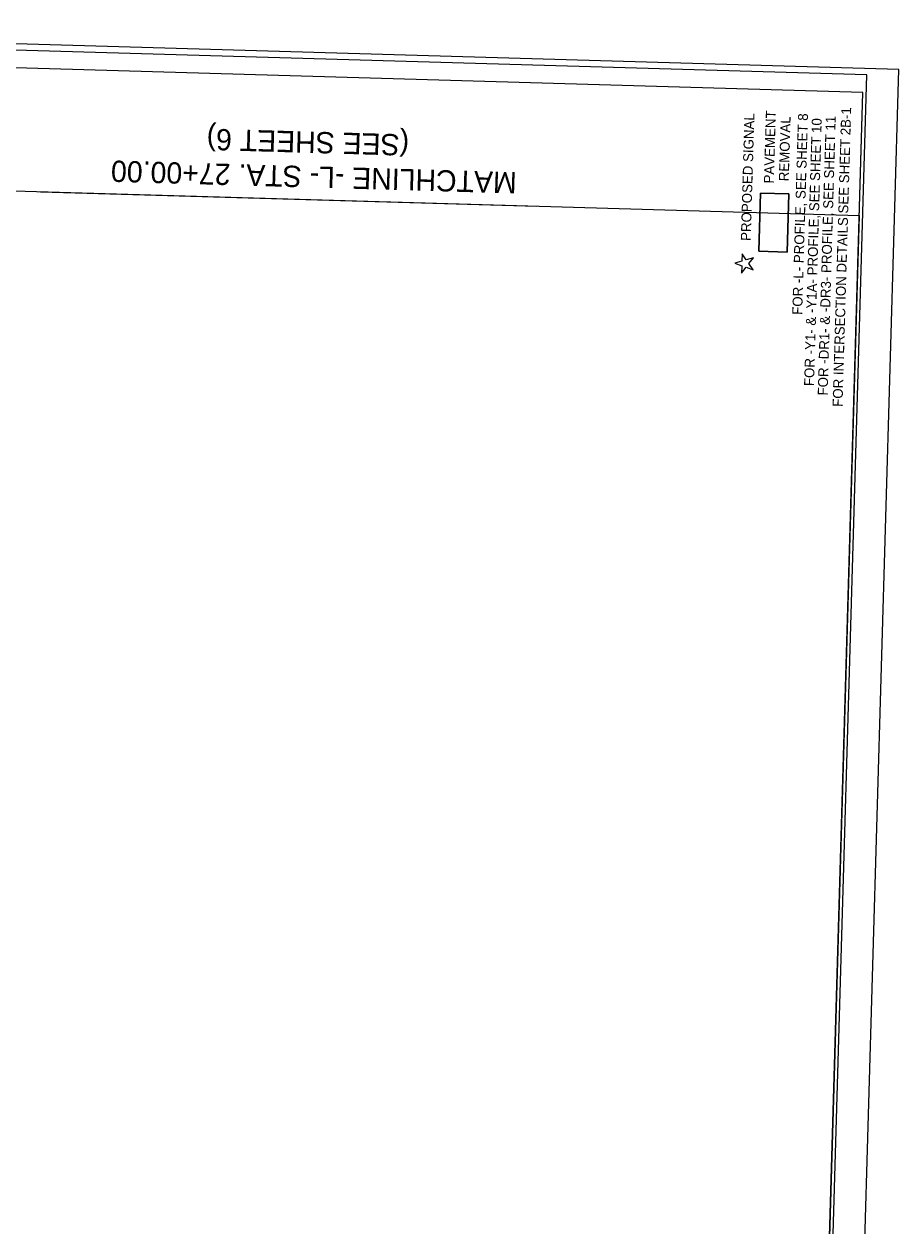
# Model space of a CAD drawing. Extents: x 2097000 to 2098148, y 684979 to 687012.
# Drawn here: x 2097532 to 2098148, y 685995 to 686842 of the extents above; entities that cross this region are included whole.
import ezdxf

# ---------------------------------------------------------------- set-up
doc = ezdxf.new("R2010")
doc.units = 0
for name, color, linetype in [('Default', 7, 'Continuous'), ('Matchline', 7, 'Continuous'), ('Matchline Text', 7, 'Continuous'), ('Prop Dimension Text', 7, 'Continuous'), ('Prop RDY Traffic Signal CELL', 7, 'Continuous'), ('Prop Rem of Exist Asph Pvmt', 7, 'Continuous'), ('Sheet Layout Plan Border', 7, 'Continuous'), ('Sheet Plot Border Inside CELL', 7, 'Continuous'), ('Sheet Plot Border Outside CELL', 7, 'Continuous'), ('Sheet Profile CELL', 7, 'Continuous')]:
    doc.layers.add(name, color=color, linetype=linetype)

msp = doc.modelspace()

# ---------------------------------------------------------------- linework, layer by layer
at = {"layer": 'Matchline'}
msp.add_line((2097543.06, 686723.93), (2097892.91, 686713.76), dxfattribs=at)
at = {"layer": 'Prop Dimension Text'}
msp.add_lwpolyline([(2098049.17, 686682.03), (2098050.36, 686722.96), (2098070.39, 686722.37), (2098069.2, 686681.45)], close=True, dxfattribs=at)
at = {"layer": 'Prop RDY Traffic Signal CELL'}
msp.add_lwpolyline([(2098037.26, 686671.81), (2098037.11, 686666.59), (2098040.3, 686670.73), (2098045.23, 686668.97), (2098042.28, 686673.29), (2098045.47, 686677.43), (2098040.46, 686675.96), (2098037.51, 686680.27), (2098037.36, 686675.05), (2098032.34, 686673.57), (2098037.26, 686671.81)], dxfattribs=at)
at = {"layer": 'Prop Rem of Exist Asph Pvmt'}
msp.add_lwpolyline([(2098069.2, 686681.45), (2098070.39, 686722.37), (2098050.36, 686722.96), (2098049.17, 686682.03), (2098069.2, 686681.45)], dxfattribs=at)
at = {"layer": 'Sheet Layout Plan Border'}
msp.add_lwpolyline([(2098090.85, 685704.42), (2097236.93, 685318.96), (2097029.37, 685324.99), (2097067.15, 686624.39), (2097254.37, 686618.95), (2097261.85, 686618.73), (2097260.99, 686589.19), (2097439.33, 686584), (2097443.49, 686726.82), (2098120, 686707.16)], close=True, dxfattribs=at)
at = {"layer": 'Sheet Plot Border Inside CELL'}
msp.add_lwpolyline([(2098077, 685140.47), (2098125.43, 686806.26), (2097070.77, 686836.92), (2097022.35, 685171.13)], close=True, dxfattribs=at)
at = {"layer": 'Sheet Plot Border Outside CELL'}
msp.add_lwpolyline([(2098099.07, 685126.82), (2098148, 686810.11), (2097048.47, 686842.07), (2096999.53, 685158.79)], close=True, dxfattribs=at)
at = {"layer": 'Sheet Profile CELL'}
msp.add_line((2098078.93, 685294.48), (2098122.52, 686793.84), dxfattribs=at)
msp.add_lwpolyline([(2097072.96, 686824.36), (2097029.37, 685324.99), (2098078.93, 685294.48), (2098122.52, 686793.84)], close=True, dxfattribs=at)

# ---------------------------------------------------------------- texts
at = {"layer": 'Default'}
msp.add_text('PROPOSED SIGNAL', height=7, rotation=88.33483, dxfattribs=at).set_placement((2098043.56, 686689.19))
at = {"layer": 'Matchline Text'}
for s, p in [('(SEE SHEET 6)', (2097803.06, 686764.26)), ('MATCHLINE -L- STA. 27+00.00', (2097878.9, 686737.67))]:
    msp.add_text(s, height=15, rotation=178.33483, dxfattribs=at).set_placement(p)
at = {"layer": 'Prop Dimension Text'}
for s, p in [('FOR INTERSECTION DETAILS SEE SHEET 2B-1', (2098108.22, 686572.3)), ('PAVEMENT', (2098059.79, 686729.65)), ('REMOVAL', (2098070.34, 686731.22)), ('FOR -L- PROFILE, SEE SHEET 8', (2098079.8, 686637.11)), ('FOR -Y1- & -Y1A- PROFILE, SEE SHEET 10', (2098088.13, 686586.91)), ('FOR -DR1- & -DR3- PROFILE, SEE SHEET 11', (2098097.74, 686580.3))]:
    msp.add_text(s, height=7, rotation=88.33483, dxfattribs=at).set_placement(p)

doc.saveas('drawing.dxf')
